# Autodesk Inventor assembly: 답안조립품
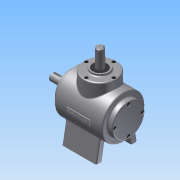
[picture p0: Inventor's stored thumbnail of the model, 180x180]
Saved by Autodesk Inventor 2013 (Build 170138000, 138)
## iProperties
Created: 2015-01
Part Number: 답안조립품
Document SubType Name: Assembly
Designer: kb54305
Author: kb54305
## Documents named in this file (15)
- C:\Users\kb54305\Desktop\450105V1024\답안조립품.iam
- C:\Users\kb54305\Desktop\450105V1024\본체.ipt
- C:\Users\kb54305\Desktop\450105V1024\공용부품\M4.ipt
- C:\Users\kb54305\Desktop\450105V1024\공용부품\메인 베벨기어.ipt
- C:\Users\kb54305\Desktop\450105V1024\공용부품\메인 축.ipt
- 메인 축.ipt
- C:\Users\kb54305\Desktop\450105V1024\공용부품\베어링 6203.ipt
- C:\Users\kb54305\Desktop\450105V1024\공용부품\서브 베벨기어.ipt
- C:\Users\kb54305\Desktop\450105V1024\공용부품\서브 축.ipt
- 서브 축.ipt
- C:\Users\kb54305\Desktop\450105V1024\공용부품\오일실.ipt
- C:\Users\kb54305\Desktop\450105V1024\공용부품\커버.ipt
- C:\Users\kb54305\Desktop\450105V1024\공용부품\커버2.ipt
- C:\Users\kb54305\Desktop\450105V1024\공용부품\키 4x4.ipt
- C:\Users\kb54305\Desktop\450105V1024\공용부품\키 5x5.ipt
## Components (12 placed, 1 different names)
1. M4:2
2. M4:3
3. M4:4
4. M4:5
5. M4:6
6. M4:7
7. M4:8
8. M4:9
9. M4:1
10. M4:10
11. M4:11
12. M4:12
